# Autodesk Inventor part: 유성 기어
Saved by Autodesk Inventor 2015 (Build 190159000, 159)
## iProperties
Created: 2026-05
Part Number: 유성 기어
Material: 일반
Document SubType Name: Modeling
Designer: 104
Density: 1 g/cm^3
Appearance: 기본값
Author: 104
Author: jhkim
Creation Date: 2026-04-27
Sending System: Autodesk Inventor 2027
Preprocessor: ST-DEVELOPER v20.1
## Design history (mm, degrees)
node "유성 기어1"
node "솔리드1"
node "기준1"
